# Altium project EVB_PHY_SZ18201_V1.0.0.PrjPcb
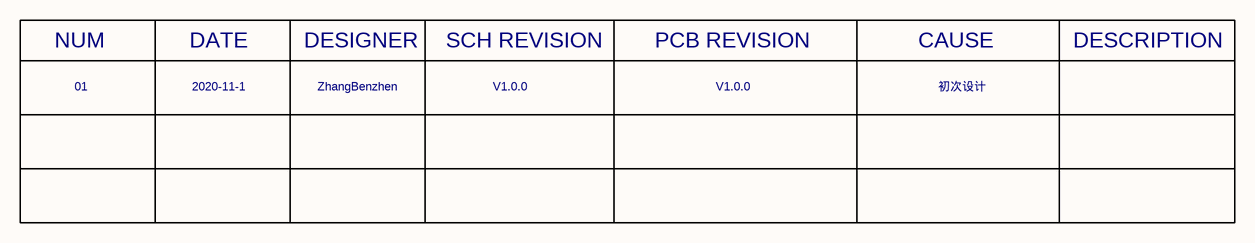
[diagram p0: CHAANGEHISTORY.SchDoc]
3 sheets, 58 parts. Net scope: flat (ports and power ports of the same name join across sheets).
Sheets:
  CHAANGEHISTORY.SchDoc
  INTERFACE.SchDoc
  SZ18201.SchDoc

## Sheet CHAANGEHISTORY.SchDoc: EVB_PHY_SZ18201_V1.0.0
size A4; Revision: V1.0.0; SheetNumber: 1; SheetTotal: 3

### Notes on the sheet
- NUM
- DATE
- DESIGNER
- SCH REVISION
- PCB REVISION
- CAUSE
- DESCRIPTION
- 01
- 2020-11-1
- ZhangBenzhen
- V1.0.0
- 初次设计

## Sheet INTERFACE.SchDoc: EVB_PHY_SZ18201_V1.0.0
size A4; Revision: V1.0.0; SheetNumber: 2; SheetTotal: 3
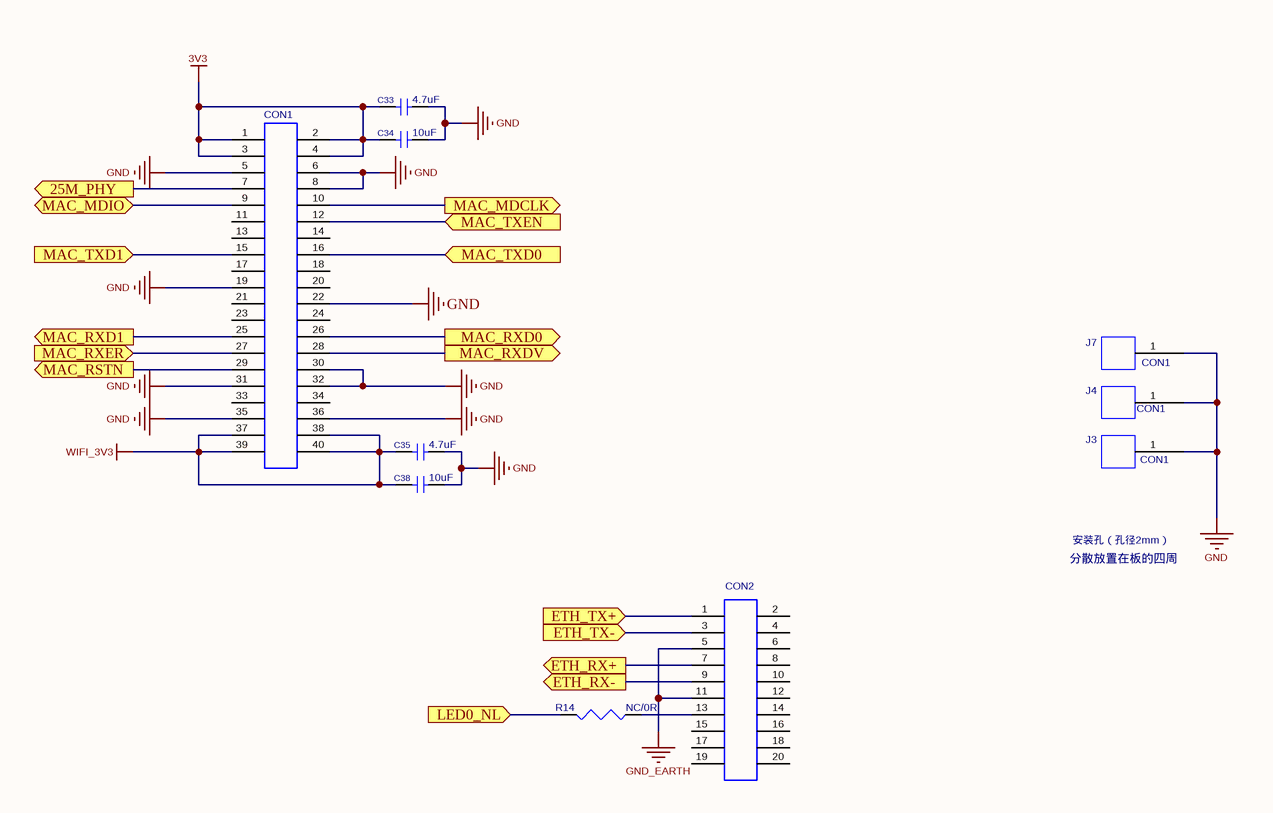
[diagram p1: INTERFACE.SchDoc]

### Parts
C33  4.7uF  [C0603]
C34  10uF  [C0805]
C35  4.7uF  [C0603]
C38  10uF  [C0805]
CON1  CON20X2_0MM5_BTB_DF12  [CON20X2_0MM5_BTB_DF12_N]  (value not drawn)
CON2  CON10X2_0MM5_BTB_DF12  [CON10X2_0MM5_BTB_DF12_N]  (value not drawn)
J3  CON1  [H_2MM2_4MM]
J4  CON1  [H_2MM2_4MM]
J7  CON1  [H_2MM2_4MM]
R14  NC/0R  [R0603]

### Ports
25M_PHY (out), ETH_RX+ (out), ETH_RX- (out), ETH_TX+ (in), ETH_TX- (in), LED0_NL (in), MAC_MDCLK (out), MAC_MDIO (bidir), MAC_RSTN (out), MAC_RXD0 (out), MAC_RXD1 (out), MAC_RXDV (out), MAC_RXER (in), MAC_TXD0 (in), MAC_TXD1 (in), MAC_TXEN (in)

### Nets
3V3: C33.1 C34.1 CON1.1 CON1.2 CON1.3 CON1.4
GND: C33.2 C34.2 C35.2 C38.2 CON1.5 CON1.6 CON1.8 CON1.19 CON1.22 CON1.30 CON1.31 CON1.32 CON1.35 CON1.36 J3.1 J4.1 J7.1
GND_EARTH: CON2.5 CON2.11
WIFI_3V3: C35.1 C38.1 CON1.37 CON1.38 CON1.39 CON1.40
25M_PHY: CON1.7 ; port 25M_PHY
ETH_RX+: CON2.7 ; port ETH_RX+
ETH_RX-: CON2.9 ; port ETH_RX-
ETH_TX+: CON2.1 ; port ETH_TX+
ETH_TX-: CON2.3 ; port ETH_TX-
LED0_NL: R14.2 ; port LED0_NL
MAC_MDCLK: CON1.10 ; port MAC_MDCLK
MAC_MDIO: CON1.9 ; port MAC_MDIO
MAC_RSTN: CON1.29 ; port MAC_RSTN
MAC_RXD0: CON1.26 ; port MAC_RXD0
MAC_RXD1: CON1.25 ; port MAC_RXD1
MAC_RXDV: CON1.28 ; port MAC_RXDV
MAC_RXER: CON1.27 ; port MAC_RXER
MAC_TXD0: CON1.16 ; port MAC_TXD0
MAC_TXD1: CON1.15 ; port MAC_TXD1
MAC_TXEN: CON1.12 ; port MAC_TXEN
NetCON2_13: CON2.13 R14.1

Not connected (* = marked no-connect by the designer): CON1 11 13 14 17 18 20 21 23 24 33 34; CON2 2 4 6 8 10 12 14 15 16 17 18 19 20

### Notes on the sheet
- 分散放置在板的四周
- 安装孔（孔径2mm）

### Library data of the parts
C33 C35 = CC0304752XX: C/C,4.7uF,10V +/-10%,0603; Catalog: 陶瓷电容
C34 C38 = CC0501063XX: C/C,10uF,16V,+/-20%,0805; Catalog: 陶瓷电容
CON1 = CNBBM4000XX: 0.5mm ，BTB2*20Pin，SMT，公座，H3.0，DF12#(3.0)-40DS-0.5; PCB DECAL: CON20X2_0MM5_BTB_DF12_BOTTOM; Catalog: Connector
CON2 = CNBBM2000XX: 0.5mm ，BTB2*10Pin，SMT，公座，H3.0，DF12#(3.0)-20DS-0.5; PCB DECAL: CON10X2_0MM5_BTB_DF12_BOTTOM; Catalog: Connector
J3 J4 J7 = CON1: Source_Path: D:\CADENCE\SPB_16.3\TOOLS\CAPTURE\LIBRARY\CONNECTOR.OLB
R14 = CR0300000XX: Res,0R,1/10W,+/-5%,0603; Remark: NC; Catalog: 贴片电阻

## Sheet SZ18201.SchDoc: EVB_PHY_SZ18201_V1.0.0
size A4; Revision: V1.0.0; SheetNumber: 3; SheetTotal: 3
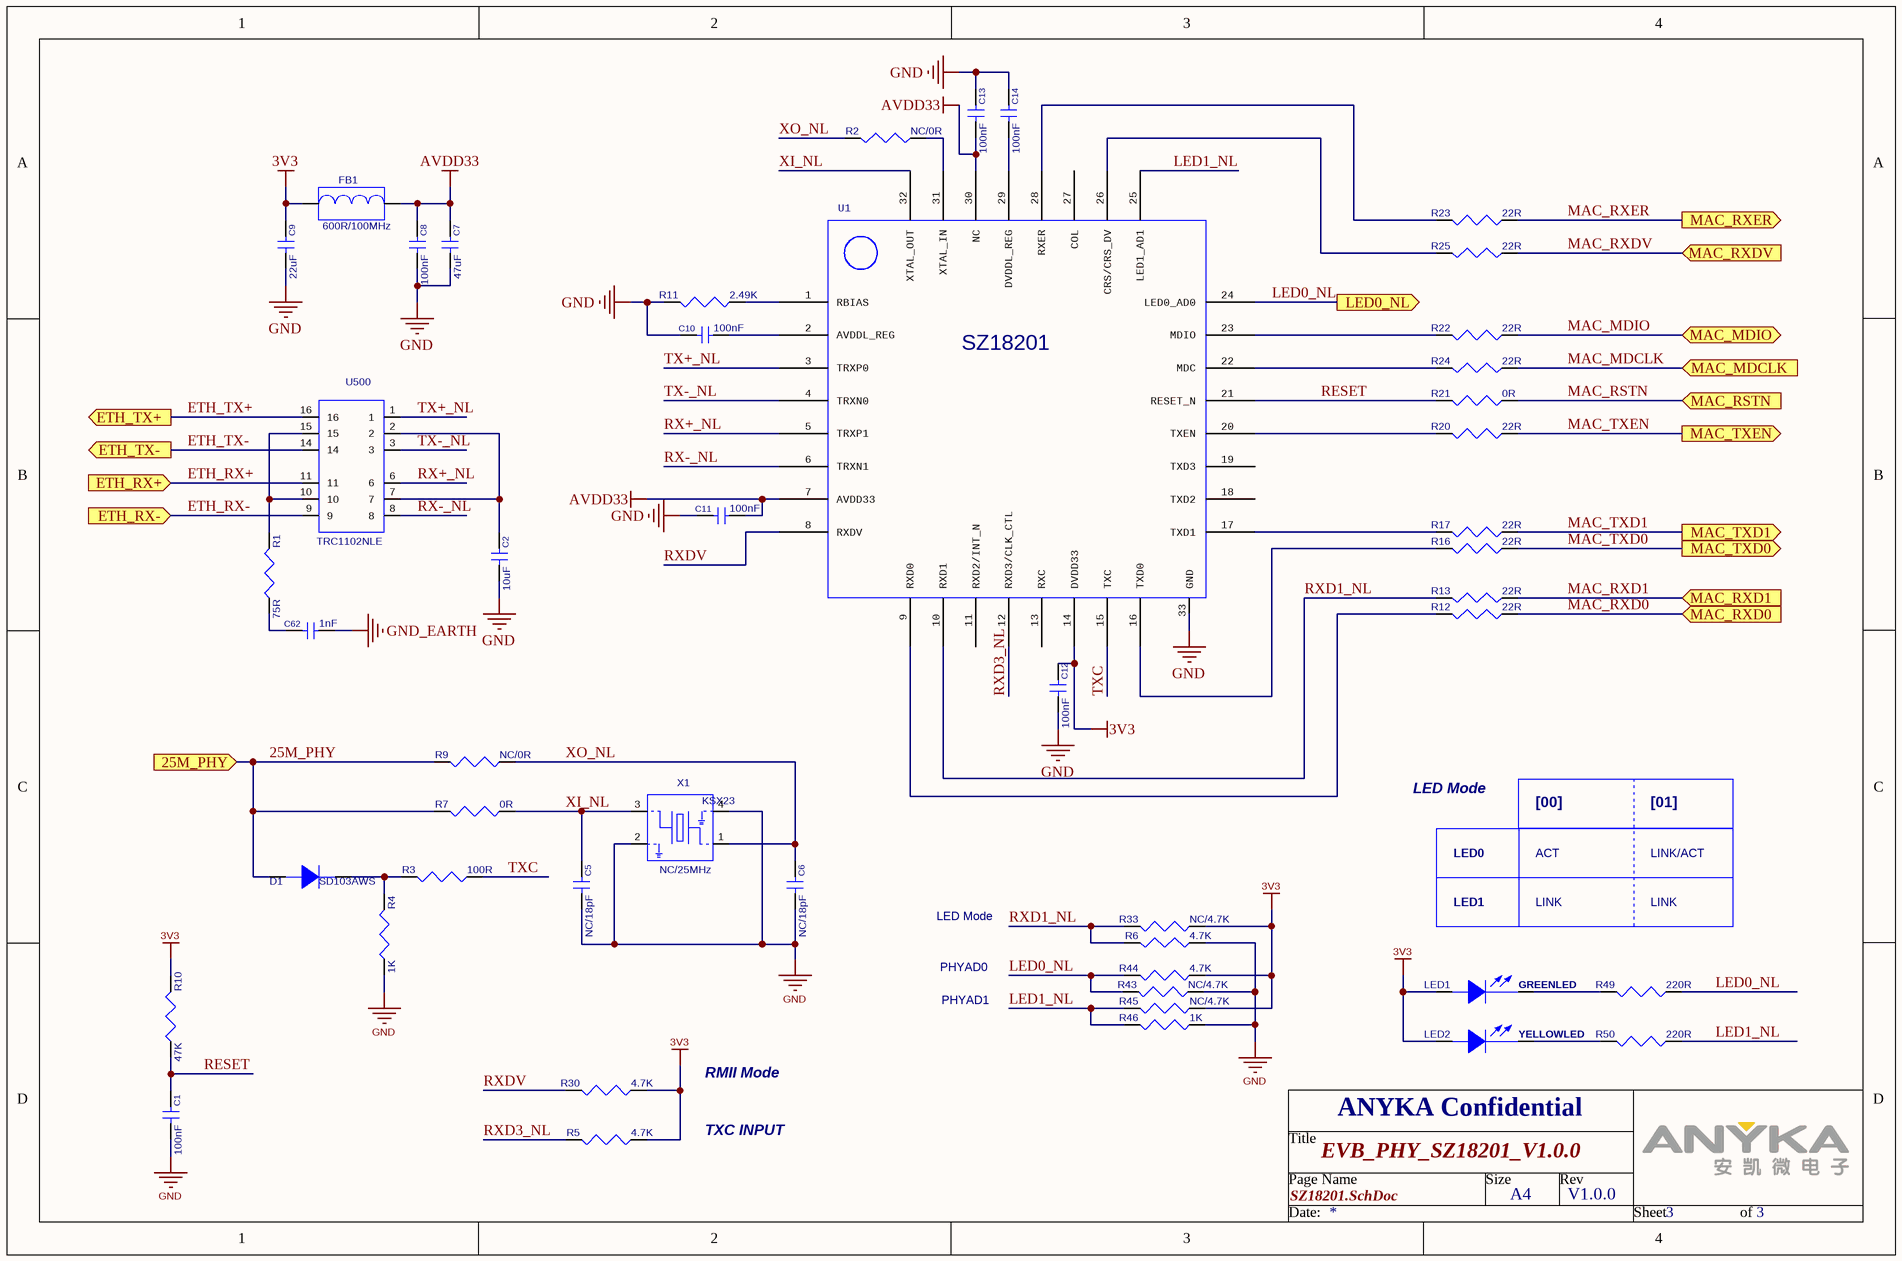
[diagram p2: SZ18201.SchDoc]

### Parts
C1  100nF  [C0603]
C2  10uF  [C0805]
C5  NC/18pF  [C0603]
C6  NC/18pF  [C0603]
C7  47uF  [C1210]
C8  100nF  [C0603]
C9  22uF  [C1210]
C10  100nF  [C0603]
C11  100nF  [C0603]
C12  100nF  [C0603]
C13  100nF  [C0603]
C14  100nF  [C0603]
C62  1nF  [C1206]
D1  value SD103AWS  [1N4148_SMD]  (hidden comment: DIODE)
FB1  600R/100MHz  [FB0603]
LED1  GREENLED  [LED0603]
LED2  YELLOWLED  [LED0603]
R1  75R  [R0603]
R2  NC/0R  [R0603]
R3  100R  [R0603]
R4  1K  [R0603]
R5  4.7K  [R0603]
R6  4.7K  [R0603]
R7  0R  [R0603]
R9  NC/0R  [R0603]
R10  47K  [R0603]
R11  2.49K  [R0603]
R12  22R  [R0603]
R13  22R  [R0603]
R16  22R  [R0603]
R17  22R  [R0603]
R20  22R  [R0603]
R21  0R  [R0603]
R22  22R  [R0603]
R23  22R  [R0603]
R24  22R  [R0603]
R25  22R  [R0603]
R30  4.7K  [R0603]
R33  NC/4.7K  [R0603]
R43  NC/4.7K  [R0603]
R44  4.7K  [R0603]
R45  NC/4.7K  [R0603]
R46  1K  [R0603]
R49  220R  [R0603]
R50  220R  [R0603]
U1  SZ18201  [QFN32_0MM5_5X5MM]  (value not drawn)
U500  TRC1102NLE  [TRC1102NLE]
X1  NC/25MHz  [3225]

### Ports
25M_PHY (in), ETH_RX+ (in), ETH_RX- (in), ETH_TX+ (out), ETH_TX- (out), LED0_NL (out), MAC_MDCLK (in), MAC_MDIO (bidir), MAC_RSTN (in), MAC_RXD0 (in), MAC_RXD1 (in), MAC_RXDV (in), MAC_RXER (out), MAC_TXD0 (out), MAC_TXD1 (out), MAC_TXEN (out)

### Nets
3V3: C9.1 C12.1 FB1.1 LED1.A LED2.A R5.1 R10.2 R30.1 R33.1 R44.1 R45.1 U1.14(DVDD33)
AVDD33: C7.1 C8.1 C11.2 C13.2 FB1.2 U1.7(AVDD33) U1.30(NC)
GND: C1.2 C2.2 C5.2 C6.2 C7.2 C8.2 C9.2 C10.1 C11.1 C12.2 C13.1 C14.1 R4.1 R6.1 R11.2 R43.1 R46.1 U1.33(GND) X1.2 X1.4
GND_EARTH: C62.2
25M_PHY: D1.A R7.2 R9.2 ; port 25M_PHY
ETH_RX+: U500.11 ; port ETH_RX+
ETH_RX-: U500.9 ; port ETH_RX-
ETH_TX+: U500.16 ; port ETH_TX+
ETH_TX-: U500.14 ; port ETH_TX-
LED0_NL: R43.2 R44.2 R49.1 U1.24(LED0_AD0) ; port LED0_NL
LED1_NL: R45.2 R46.2 R50.1 U1.25(LED1_AD1)
MAC_MDCLK: R24.1 ; port MAC_MDCLK
MAC_MDIO: R22.1 ; port MAC_MDIO
MAC_RSTN: R21.1 ; port MAC_RSTN
MAC_RXD0: R12.1 ; port MAC_RXD0
MAC_RXD1: R13.1 ; port MAC_RXD1
MAC_RXDV: R25.1 ; port MAC_RXDV
MAC_RXER: R23.1 ; port MAC_RXER
MAC_TXD0: R16.1 ; port MAC_TXD0
MAC_TXD1: R17.1 ; port MAC_TXD1
MAC_TXEN: R20.1 ; port MAC_TXEN
RESET: C1.1 R10.1 R21.2 U1.21(RESET_N)
RX+_NL: U1.5(TRXP1) U500.6
RX-_NL: U1.6(TRXN1) U500.8
RXD1_NL: R6.2 R13.2 R33.2 U1.10(RXD1)
RXD3_NL: R5.2 U1.12(RXD3/CLK_CTL)
RXDV: R30.2 U1.8(RXDV)
TX+_NL: U1.3(TRXP0) U500.1
TX-_NL: U1.4(TRXN0) U500.3
TXC: R3.1 U1.15(TXC)
XI_NL: C5.1 R7.1 U1.32(XTAL_OUT) X1.3
XO_NL: C6.1 R2.2 R9.1 X1.1
NetC2_1: C2.1 U500.2 U500.7
NetC10_2: C10.2 U1.2(AVDDL_REG)
NetC14_2: C14.2 U1.29(DVDDL_REG)
NetC62_1: C62.1 R1.1
NetD1_K: D1.K R3.2 R4.2
NetLED1_K: LED1.K R49.2
NetLED2_K: LED2.K R50.2
NetR1_2: R1.2 U500.10 U500.15
NetR2_1: R2.1 U1.31(XTAL_IN)
NetR11_1: R11.1 U1.1(RBIAS)
NetR12_2: R12.2 U1.9(RXD0)
NetR16_2: R16.2 U1.16(TXD0)
NetR17_2: R17.2 U1.17(TXD1)
NetR20_2: R20.2 U1.20(TXEN)
NetR22_2: R22.2 U1.23(MDIO)
NetR23_2: R23.2 U1.28(RXER)
NetR24_2: R24.2 U1.22(MDC)
NetR25_2: R25.2 U1.26(CRS/CRS_DV)

Not connected (* = marked no-connect by the designer): U1 11(RXD2/INT_N) 13(RXC) 18(TXD2) 19(TXD3) 27(COL)

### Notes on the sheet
- LED Mode
- LED0
- [00]
- ACT
- [01]
- LINK/ACT
- LED1
- LINK
- PHYAD0
- PHYAD1
- RMII Mode
- TXC INPUT

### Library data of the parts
C1 C8 C10-C14 = CC0301040XX: C/C,100nF,25V,+/-5%,0603; Catalog: 陶瓷电容
C2 = CC0501063XX: C/C,10uF,16V,+/-20%,0805; Catalog: 陶瓷电容
C5 C6 = CC0301800XX: C/C,18pF,25V,+/-5%,0603; Remark: NC; Catalog: 陶瓷电容
C7 = CC1004760XX: C/C,47uF,10V,+/-10%,1210; Catalog: 陶瓷电容
C9 = CC1002260XX: C/C,22uF,16V,+/-10%,1210; Catalog: 陶瓷电容
C62 = CC0601021XX: C/C,1nF,2KV,+/-10%,1206; Catalog: 陶瓷电容
D1 = SD103AWS: 1N4148_SMD( ROUND); PART_NUMBER: XXXXXXXX
FB1 = BE0306011XX: BLM18BD601SN1, 600R@100MHz; SOURCE_PATH: D:\PROGRAM FILES\ORCAD\ORCAD_10.5\TOOLS\CAPTURE\LIBRARY\DISCRETE.OLB; Catalog: 贴片磁珠
LED1 = LE03GXX00XX: GREENLED,0603; Catalog: 二极管
LED2 = LE03YXX00XX: YELLOW,LED0603; Catalog: 二极管
R1 = CR0307500XX: Res,75R,1/10W,+/-5%,0603; Catalog: 贴片电阻
R2 = CR0300000XX: as R14 on sheet INTERFACE
R3 = CR0301010XX: Res,100R,1/10W,+/-5%,0603; Catalog: 贴片电阻
R4 R46 = CR0301020XX: Res,1K,1/10W,+/-5%,0603; Catalog: 贴片电阻
R5 R6 R30 R44 = CR0304720XX: Res,4.7K,1/10W,+/-5%,0603; Catalog: 贴片电阻
R7 R9 R21 = CR0300000XX: Res,0R,1/10W,+/-5%,0603; Catalog: 贴片电阻
R10 = CR0347020XX: Res,47K,1/10W,+/-1%,0603; Catalog: 贴片电阻
R11 = CR0324910XX: Res,2.49K,1/10W,+/-1%,0603; Catalog: 贴片电阻
R12 R13 R16 R17 R20 R22-R25 = CR0302200XX: Res,22R,1/10W,+/-5%,0603; Catalog: 贴片电阻
R33 R43 R45 = CR0304720XX: Res,4.7K,1/10W,+/-5%,0603; Remark: NC; Catalog: 贴片电阻
R49 R50 = CR0302211XX: Res,220R,1/10W,+/-1%,0603; Catalog: 贴片电阻
U1 = JCQFNPY04XX: Ethernet PHY,SZ18201,QFN32; PCB DECAL: RTL8201F_QFN32_0MM5_5X5MM; Source_Path: F:\WORK_SPACE\ERIC\RTL8201\RTL8201F\SCHEMATIC\QFN32_RMII_MII\REFERENCE\V1.4\RTL8201F(E)_COLAY_REFERENCE_1.4.DSN; Value: RTL8201F-CG; Catalog: 集成电路
U500 = TFSMD1601XX: Transformer,Trxcom,TRC1188NL,16pin; Part_RNEfNErNEncNE: NU704; room: ethernet; NC: 4,5,12,13; Source_Path: D:\MOBILE_PROJECT\WINCE\WINCE-7802\LIBRARY1.OLB; Catalog: 网络变压器
X1 = XR0025MS0XX: 25MHz,CL=10pF,10ppm,3225; PCB DECAL: DSX3225; Remark: NC; Catalog: 晶振

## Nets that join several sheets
3V3: INTERFACE (6 pins), SZ18201 (12 pins)
GND: INTERFACE (17 pins), SZ18201 (20 pins)
GND_EARTH: INTERFACE (CON2.5 CON2.11), SZ18201 (C62.2)
25M_PHY: INTERFACE (CON1.7), SZ18201 (D1.A R7.2 R9.2)
ETH_RX+: INTERFACE (CON2.7), SZ18201 (U500.11)
ETH_RX-: INTERFACE (CON2.9), SZ18201 (U500.9)
ETH_TX+: INTERFACE (CON2.1), SZ18201 (U500.16)
ETH_TX-: INTERFACE (CON2.3), SZ18201 (U500.14)
LED0_NL: INTERFACE (R14.2), SZ18201 (R43.2 R44.2 R49.1 U1.24)
MAC_MDCLK: INTERFACE (CON1.10), SZ18201 (R24.1)
MAC_MDIO: INTERFACE (CON1.9), SZ18201 (R22.1)
MAC_RSTN: INTERFACE (CON1.29), SZ18201 (R21.1)
MAC_RXD0: INTERFACE (CON1.26), SZ18201 (R12.1)
MAC_RXD1: INTERFACE (CON1.25), SZ18201 (R13.1)
MAC_RXDV: INTERFACE (CON1.28), SZ18201 (R25.1)
MAC_RXER: INTERFACE (CON1.27), SZ18201 (R23.1)
MAC_TXD0: INTERFACE (CON1.16), SZ18201 (R16.1)
MAC_TXD1: INTERFACE (CON1.15), SZ18201 (R17.1)
MAC_TXEN: INTERFACE (CON1.12), SZ18201 (R20.1)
